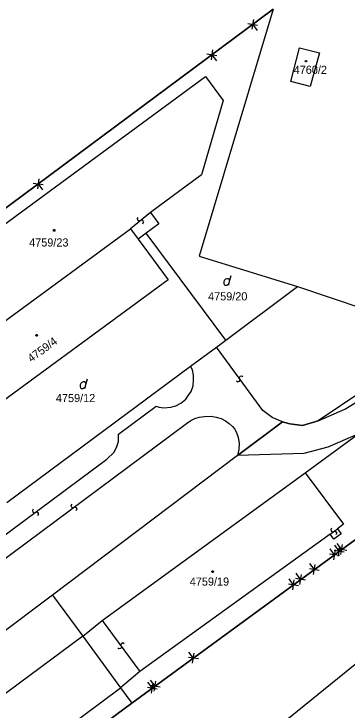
# Model space of a CAD drawing. Extents: x -266179 to -264727, y -1243225 to -1241702.
# Drawn here: x -265508.7 to -265443.1, y -1242990.2 to -1242853.4 of the extents above; entities that cross this region are included whole.
import ezdxf

# ---------------------------------------------------------------- set-up
doc = ezdxf.new("R2010")
doc.units = 0
for name, color, linetype in [('Vrstva 1', 7, 'Continuous'), ('Vrstva 2', 7, 'Continuous'), ('Vrstva 21', 7, 'Continuous'), ('Vrstva 63', 7, 'Continuous')]:
    doc.layers.add(name, color=color, linetype=linetype)

msp = doc.modelspace()

# ---------------------------------------------------------------- linework, layer by layer
at = {"layer": 'Vrstva 1'}
for p, q in [((-265515.95, -1242895.72), (-265457.68, -1242852.47)), ((-265457.68, -1242852.47), (-265472.19, -1242900.99)), ((-265454.19, -1242866.65), (-265452.5, -1242860.05)), ((-265452.5, -1242860.05), (-265448.58, -1242861.02)), ((-265448.58, -1242861.02), (-265450.37, -1242867.68)), ((-265533.81, -1242911.88), (-265470.99, -1242865.69)), ((-265470.99, -1242865.69), (-265467.52, -1242870.44)), ((-265450.37, -1242867.68), (-265454.19, -1242866.65)), ((-265467.52, -1242870.44), (-265471.74, -1242885.06)), ((-265471.74, -1242885.06), (-265481.78, -1242892.43)), ((-265481.78, -1242892.43), (-265480.14, -1242894.64)), ((-265480.14, -1242894.64), (-265482.62, -1242896.5)), ((-265524.63, -1242924.18), (-265485.75, -1242895.63)), ((-265485.75, -1242895.63), (-265484.22, -1242897.69)), ((-265482.62, -1242896.5), (-265484.22, -1242897.69)), ((-265467, -1242917.56), (-265482.62, -1242896.5)), ((-265484.22, -1242897.69), (-265478.33, -1242905.64)), ((-265472.19, -1242900.99), (-265452.9, -1242907)), ((-265466.22, -1242905.74), (-265465.95, -1242904.84)), ((-265478.33, -1242905.64), (-265517.27, -1242934.21)), ((-265467, -1242917.56), (-265452.9, -1242907)), ((-265452.9, -1242907), (-265424.1, -1242916.7)), ((-265424.1, -1242916.7), (-265448.82, -1242933.39)), ((-265468.78, -1242918.89), (-265467, -1242917.56)), ((-265473.9, -1242922.67), (-265468.78, -1242918.89)), ((-265510.08, -1242949.43), (-265473.9, -1242922.67)), ((-265494.48, -1242926.02), (-265494.21, -1242925.12)), ((-265455.85, -1242933.61), (-265464.66, -1242940.23)), ((-265454.37, -1242933.95), (-265455.85, -1242933.61)), ((-265448.82, -1242933.39), (-265451.88, -1242934.29)), ((-265451.88, -1242934.29), (-265454.37, -1242933.95)), ((-265464.66, -1242940.23), (-265501.08, -1242967.63)), ((-265491.3, -1242972.6), (-265451.35, -1242943.61)), ((-265451.35, -1242943.61), (-265443.84, -1242953.71)), ((-265443.84, -1242953.71), (-265445.03, -1242954.59)), ((-265445.03, -1242954.59), (-265444.3, -1242955.57)), ((-265485.47, -1242988.9), (-265441.55, -1242956.78)), ((-265446.48, -1242955.67), (-265483.87, -1242982.65)), ((-265445.76, -1242956.65), (-265446.48, -1242955.67)), ((-265444.3, -1242955.57), (-265445.76, -1242956.65)), ((-265501.08, -1242967.63), (-265512.63, -1242976.32)), ((-265501.08, -1242967.63), (-265495.14, -1242975.72)), ((-265495.14, -1242975.72), (-265491.3, -1242972.6)), ((-265495.14, -1242975.72), (-265534.92, -1243005.24)), ((-265495.14, -1242975.72), (-265487.69, -1242985.87)), ((-265475.52, -1243008.72), (-265434.39, -1242975.43)), ((-265483.87, -1242982.65), (-265487.69, -1242985.87)), ((-265527.48, -1243015.25), (-265487.69, -1242985.87)), ((-265487.69, -1242985.87), (-265485.47, -1242988.9)), ((-265485.47, -1242988.9), (-265493, -1242994.41))]:
    msp.add_line(p, q, dxfattribs=at)
for points in [[(-265451.11, -1242862.53), (-265451.02, -1242862.68), (-265451.11, -1242862.83), (-265451.29, -1242862.83), (-265451.38, -1242862.68), (-265451.29, -1242862.53)], [(-265500.66, -1242895.77), (-265500.57, -1242895.92), (-265500.66, -1242896.07), (-265500.84, -1242896.07), (-265500.93, -1242895.92), (-265500.84, -1242895.77)], [(-265504.11, -1242916.41), (-265504.02, -1242916.56), (-265504.11, -1242916.71), (-265504.29, -1242916.71), (-265504.38, -1242916.56), (-265504.29, -1242916.41)], [(-265469.48, -1242962.87), (-265469.39, -1242963.02), (-265469.48, -1242963.17), (-265469.66, -1242963.17), (-265469.75, -1242963.02), (-265469.66, -1242962.87)]]:
    msp.add_lwpolyline(points, close=True, dxfattribs=at)
for points in [[(-265466.4, -1242906.73), (-265466.4, -1242906.46), (-265466.22, -1242905.74), (-265466.31, -1242905.56), (-265466.49, -1242905.47), (-265466.76, -1242905.47), (-265467.03, -1242905.56), (-265467.21, -1242905.74), (-265467.39, -1242906.01), (-265467.39, -1242906.37), (-265467.3, -1242906.64), (-265467.12, -1242906.73), (-265466.85, -1242906.73), (-265466.67, -1242906.64), (-265466.4, -1242906.46)], [(-265494.66, -1242927.01), (-265494.66, -1242926.74), (-265494.48, -1242926.02), (-265494.57, -1242925.84), (-265494.75, -1242925.75), (-265495.02, -1242925.75), (-265495.29, -1242925.84), (-265495.47, -1242926.02), (-265495.65, -1242926.29), (-265495.65, -1242926.65), (-265495.56, -1242926.92), (-265495.38, -1242927.01), (-265495.11, -1242927.01), (-265494.93, -1242926.92), (-265494.66, -1242926.74)]]:
    msp.add_lwpolyline(points, dxfattribs=at)
at = {"layer": 'Vrstva 2'}
for p, q in [((-265481.78, -1242892.43), (-265485.75, -1242895.63)), ((-265459.7, -1242931.35), (-265468.78, -1242918.89)), ((-265451.35, -1242943.61), (-265419.11, -1242919.89)), ((-265473.54, -1242923.36), (-265473.9, -1242922.67)), ((-265473.34, -1242924.41), (-265473.54, -1242923.36)), ((-265473.43, -1242926.51), (-265473.31, -1242925.33)), ((-265473.31, -1242925.33), (-265473.34, -1242924.41)), ((-265473.79, -1242927.61), (-265473.43, -1242926.51)), ((-265474.3, -1242928.34), (-265473.79, -1242927.61)), ((-265475.86, -1242929.91), (-265474.82, -1242929.13)), ((-265474.82, -1242929.13), (-265474.3, -1242928.34)), ((-265488.08, -1242936.03), (-265480.66, -1242930.51)), ((-265480.66, -1242930.51), (-265480.08, -1242930.73)), ((-265480.08, -1242930.73), (-265479.15, -1242930.86)), ((-265479.15, -1242930.86), (-265477.81, -1242930.73)), ((-265477.81, -1242930.73), (-265476.82, -1242930.44)), ((-265476.82, -1242930.44), (-265475.86, -1242929.91)), ((-265457.89, -1242932.71), (-265459.7, -1242931.35)), ((-265474.69, -1242933.88), (-265473.86, -1242933.31)), ((-265473.86, -1242933.31), (-265473.05, -1242932.94)), ((-265473.05, -1242932.94), (-265472.21, -1242932.69)), ((-265472.21, -1242932.69), (-265471.18, -1242932.51)), ((-265471.18, -1242932.51), (-265469.88, -1242932.49)), ((-265469.88, -1242932.49), (-265468.85, -1242932.64)), ((-265468.85, -1242932.64), (-265467.87, -1242932.94)), ((-265467.87, -1242932.94), (-265467.03, -1242933.36)), ((-265467.03, -1242933.36), (-265466.3, -1242933.89)), ((-265455.85, -1242933.61), (-265457.89, -1242932.71)), ((-265519.07, -1242966.85), (-265474.69, -1242933.88)), ((-265466.3, -1242933.89), (-265465.68, -1242934.47)), ((-265465.68, -1242934.47), (-265465.22, -1242935.04)), ((-265488.12, -1242937.35), (-265488.08, -1242936.03)), ((-265465.22, -1242935.04), (-265464.84, -1242935.85)), ((-265464.84, -1242935.85), (-265464.54, -1242936.65)), ((-265488.39, -1242938.5), (-265488.12, -1242937.35)), ((-265464.54, -1242936.65), (-265464.38, -1242937.8)), ((-265489.01, -1242939.59), (-265488.39, -1242938.5)), ((-265464.4, -1242939), (-265464.66, -1242940.23)), ((-265464.38, -1242937.8), (-265464.4, -1242939)), ((-265490.38, -1242940.92), (-265489.01, -1242939.59)), ((-265518.51, -1242961.83), (-265490.38, -1242940.92)), ((-265446.48, -1242955.67), (-265445.03, -1242954.59)), ((-265491.3, -1242972.6), (-265483.87, -1242982.65))]:
    msp.add_line(p, q, dxfattribs=at)
for points in [[(-265483.333, -1242894.645), (-265483.161, -1242894.365), (-265483.264, -1242894.063), (-265483.529, -1242893.956), (-265484.044, -1242894.114), (-265484.31, -1242893.943), (-265484.355, -1242893.632), (-265484.197, -1242893.415)], [(-265464.875, -1242925.522), (-265464.604, -1242925.707), (-265464.297, -1242925.619), (-265464.177, -1242925.359), (-265464.31, -1242924.837), (-265464.127, -1242924.579), (-265463.814, -1242924.55), (-265463.605, -1242924.718)], [(-265497.287, -1242949.733), (-265497.47, -1242950.006), (-265497.38, -1242950.313), (-265497.118, -1242950.43), (-265496.598, -1242950.292), (-265496.338, -1242950.473), (-265496.306, -1242950.786), (-265496.473, -1242950.997)], [(-265504.852, -1242950.743), (-265505.035, -1242951.016), (-265504.945, -1242951.323), (-265504.683, -1242951.44), (-265504.163, -1242951.302), (-265503.903, -1242951.483), (-265503.871, -1242951.796), (-265504.038, -1242952.007)], [(-265446.163, -1242954.499), (-265446.346, -1242954.772), (-265446.255, -1242955.078), (-265445.993, -1242955.195), (-265445.473, -1242955.057), (-265445.213, -1242955.238), (-265445.18, -1242955.55), (-265445.347, -1242955.761)], [(-265486.952, -1242977.219), (-265487.225, -1242977.035), (-265487.532, -1242977.125), (-265487.649, -1242977.387), (-265487.513, -1242977.908), (-265487.695, -1242978.166), (-265488.007, -1242978.198), (-265488.218, -1242978.031)]]:
    msp.add_lwpolyline(points, dxfattribs=at)
at = {"layer": 'Vrstva 21'}
for p, q in [((-265515.95, -1242895.72), (-265457.68, -1242852.47)), ((-265457.68, -1242852.47), (-265515.95, -1242895.72)), ((-265462.676, -1242855.304), (-265460.717, -1242855.592)), ((-265461.552, -1242854.469), (-265461.841, -1242856.427)), ((-265461.696, -1242855.448), (-265460.802, -1242856.652)), ((-265469.579, -1242860.433), (-265469.868, -1242862.391)), ((-265470.703, -1242861.268), (-265468.744, -1242861.556)), ((-265469.723, -1242861.412), (-265468.829, -1242862.616)), ((-265504.886, -1242886.634), (-265502.927, -1242886.922)), ((-265503.762, -1242885.799), (-265504.051, -1242887.757)), ((-265503.907, -1242886.778), (-265503.012, -1242887.982)), ((-265441.55, -1242956.78), (-265485.47, -1242988.9)), ((-265485.47, -1242988.9), (-265441.55, -1242956.78)), ((-265444.674, -1242959.035), (-265445.554, -1242957.821)), ((-265444.177, -1242958.686), (-265445.058, -1242957.472)), ((-265444.829, -1242960.013), (-265444.518, -1242958.058)), ((-265444.333, -1242959.664), (-265444.021, -1242957.709)), ((-265444.608, -1242959.884), (-265446.564, -1242959.58)), ((-265445.586, -1242959.732), (-265446.471, -1242958.521)), ((-265445.738, -1242960.71), (-265445.434, -1242958.753)), ((-265443.696, -1242959.191), (-265445.651, -1242958.879)), ((-265443.199, -1242958.842), (-265445.155, -1242958.531)), ((-265449.564, -1242962.622), (-265450.447, -1242961.41)), ((-265449.718, -1242963.6), (-265449.41, -1242961.644)), ((-265452.273, -1242964.557), (-265453.153, -1242963.342)), ((-265452.428, -1242965.534), (-265452.117, -1242963.579)), ((-265448.586, -1242962.776), (-265450.542, -1242962.468)), ((-265453.658, -1242965.635), (-265454.543, -1242964.424)), ((-265453.81, -1242966.613), (-265453.506, -1242964.656)), ((-265451.295, -1242964.713), (-265453.25, -1242964.401)), ((-265452.68, -1242965.786), (-265454.636, -1242965.483)), ((-265472.384, -1242980.197), (-265474.34, -1242979.894)), ((-265473.362, -1242980.045), (-265474.248, -1242978.835)), ((-265473.514, -1242981.024), (-265473.21, -1242979.067)), ((-265481.434, -1242985.948), (-265482.32, -1242984.737)), ((-265479.916, -1242985.705), (-265481.872, -1242985.401)), ((-265480.894, -1242985.553), (-265481.779, -1242984.343)), ((-265481.586, -1242986.927), (-265481.282, -1242984.97)), ((-265481.046, -1242986.532), (-265480.742, -1242984.575)), ((-265480.456, -1242986.1), (-265482.412, -1242985.796)), ((-265485.47, -1242988.9), (-265493, -1242994.41)), ((-265493, -1242994.41), (-265485.47, -1242988.9))]:
    msp.add_line(p, q, dxfattribs=at)
at = {"layer": 'Vrstva 63'}
for p, q in [((-265443.56, -1242931.11), (-265421.58, -1242917.55)), ((-265448.82, -1242933.39), (-265443.56, -1242931.11)), ((-265464.66, -1242940.23), (-265455.85, -1242933.61)), ((-265455.85, -1242933.61), (-265454.37, -1242933.95)), ((-265451.88, -1242934.29), (-265448.82, -1242933.39)), ((-265454.37, -1242933.95), (-265451.88, -1242934.29)), ((-265441, -1242936), (-265446.94, -1242938.57)), ((-265446.94, -1242938.57), (-265451.63, -1242939.78)), ((-265451.63, -1242939.78), (-265464.66, -1242940.23))]:
    msp.add_line(p, q, dxfattribs=at)

# ---------------------------------------------------------------- texts
at = {"layer": 'Vrstva 1'}
for s, p in [('4760/2', (-265453.626, -1242865.18)), ('4759/23', (-265505.667, -1242899.12)), ('4759/20', (-265470.467, -1242909.71)), ('4759/12', (-265500.404, -1242929.7)), ('4759/19', (-265474.07, -1242965.78))]:
    msp.add_text(s, height=1.6, dxfattribs=at).set_placement(p)
msp.add_text('4759/4', height=1.6, rotation=36.26823, dxfattribs=at).set_placement((-265505.245, -1242921.967))

doc.saveas('drawing.dxf')
